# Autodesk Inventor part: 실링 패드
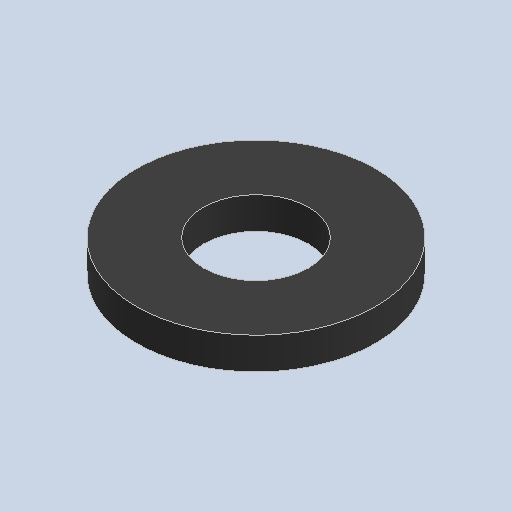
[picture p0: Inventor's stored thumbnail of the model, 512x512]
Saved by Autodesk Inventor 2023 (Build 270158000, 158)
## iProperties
Created: 2024-09
Part Number: 실링 패드
Material: 고무
Document SubType Name: Modeling
Designer: asung
Density: 0.93 g/cm^3
Appearance: 기본값
Author: jhkim
Sending System: Autodesk Inventor 2025
Preprocessor: ST-DEVELOPER v20
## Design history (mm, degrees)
feature "솔리드1"
node "솔리드2"
